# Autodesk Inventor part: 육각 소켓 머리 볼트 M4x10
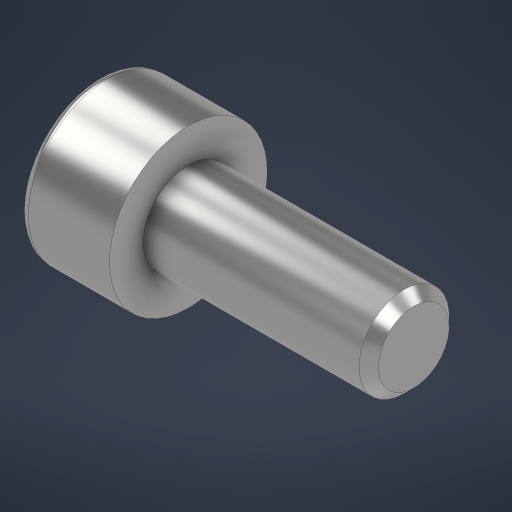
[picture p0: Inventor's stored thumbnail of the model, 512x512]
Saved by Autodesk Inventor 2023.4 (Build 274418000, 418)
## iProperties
Created: 2024-05
Part Number: 육각 소켓 머리 볼트 M4x10
Material: 강철, 연강
Description: 6각머리 태핑 나사
Document SubType Name: Modeling
Designer: Edu03
Density: 7.85 g/cm^3
Appearance: 기본값
Sending System: Autodesk Inventor 2025
Preprocessor: ST-DEVELOPER v20
Author: jhkim
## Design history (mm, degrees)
node "육각 소켓 머리 볼트 M4x101"
node "솔리드1"
body "Solid1"
